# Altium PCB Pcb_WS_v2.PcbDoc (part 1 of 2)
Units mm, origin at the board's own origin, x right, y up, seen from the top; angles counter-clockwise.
Board outline 100 x 100 mm, 2 copper layers (Top Layer, Bottom Layer); 79 components, 52 nets, 324 pads, 930 vias.
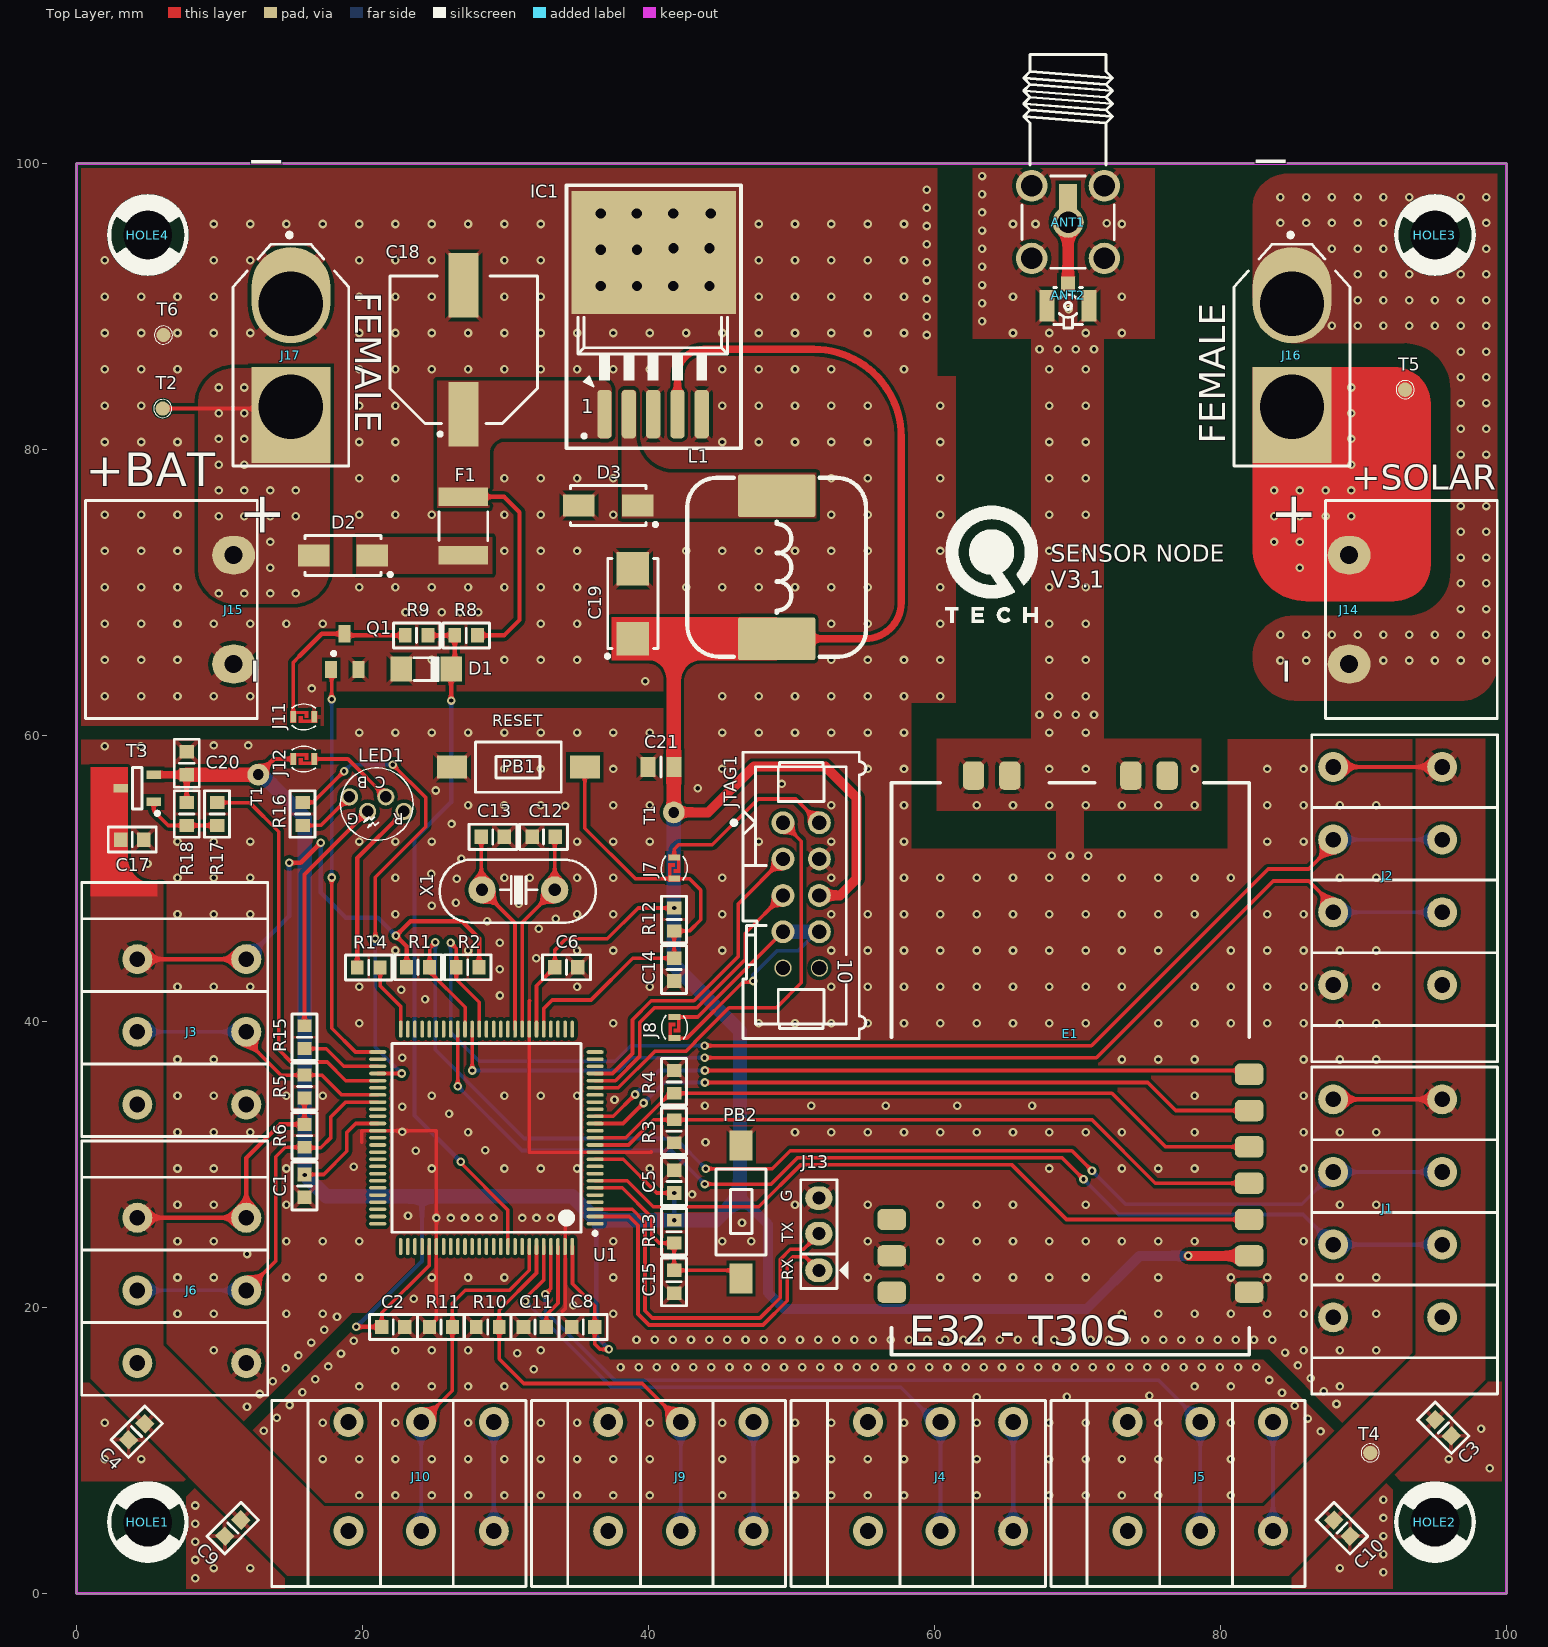
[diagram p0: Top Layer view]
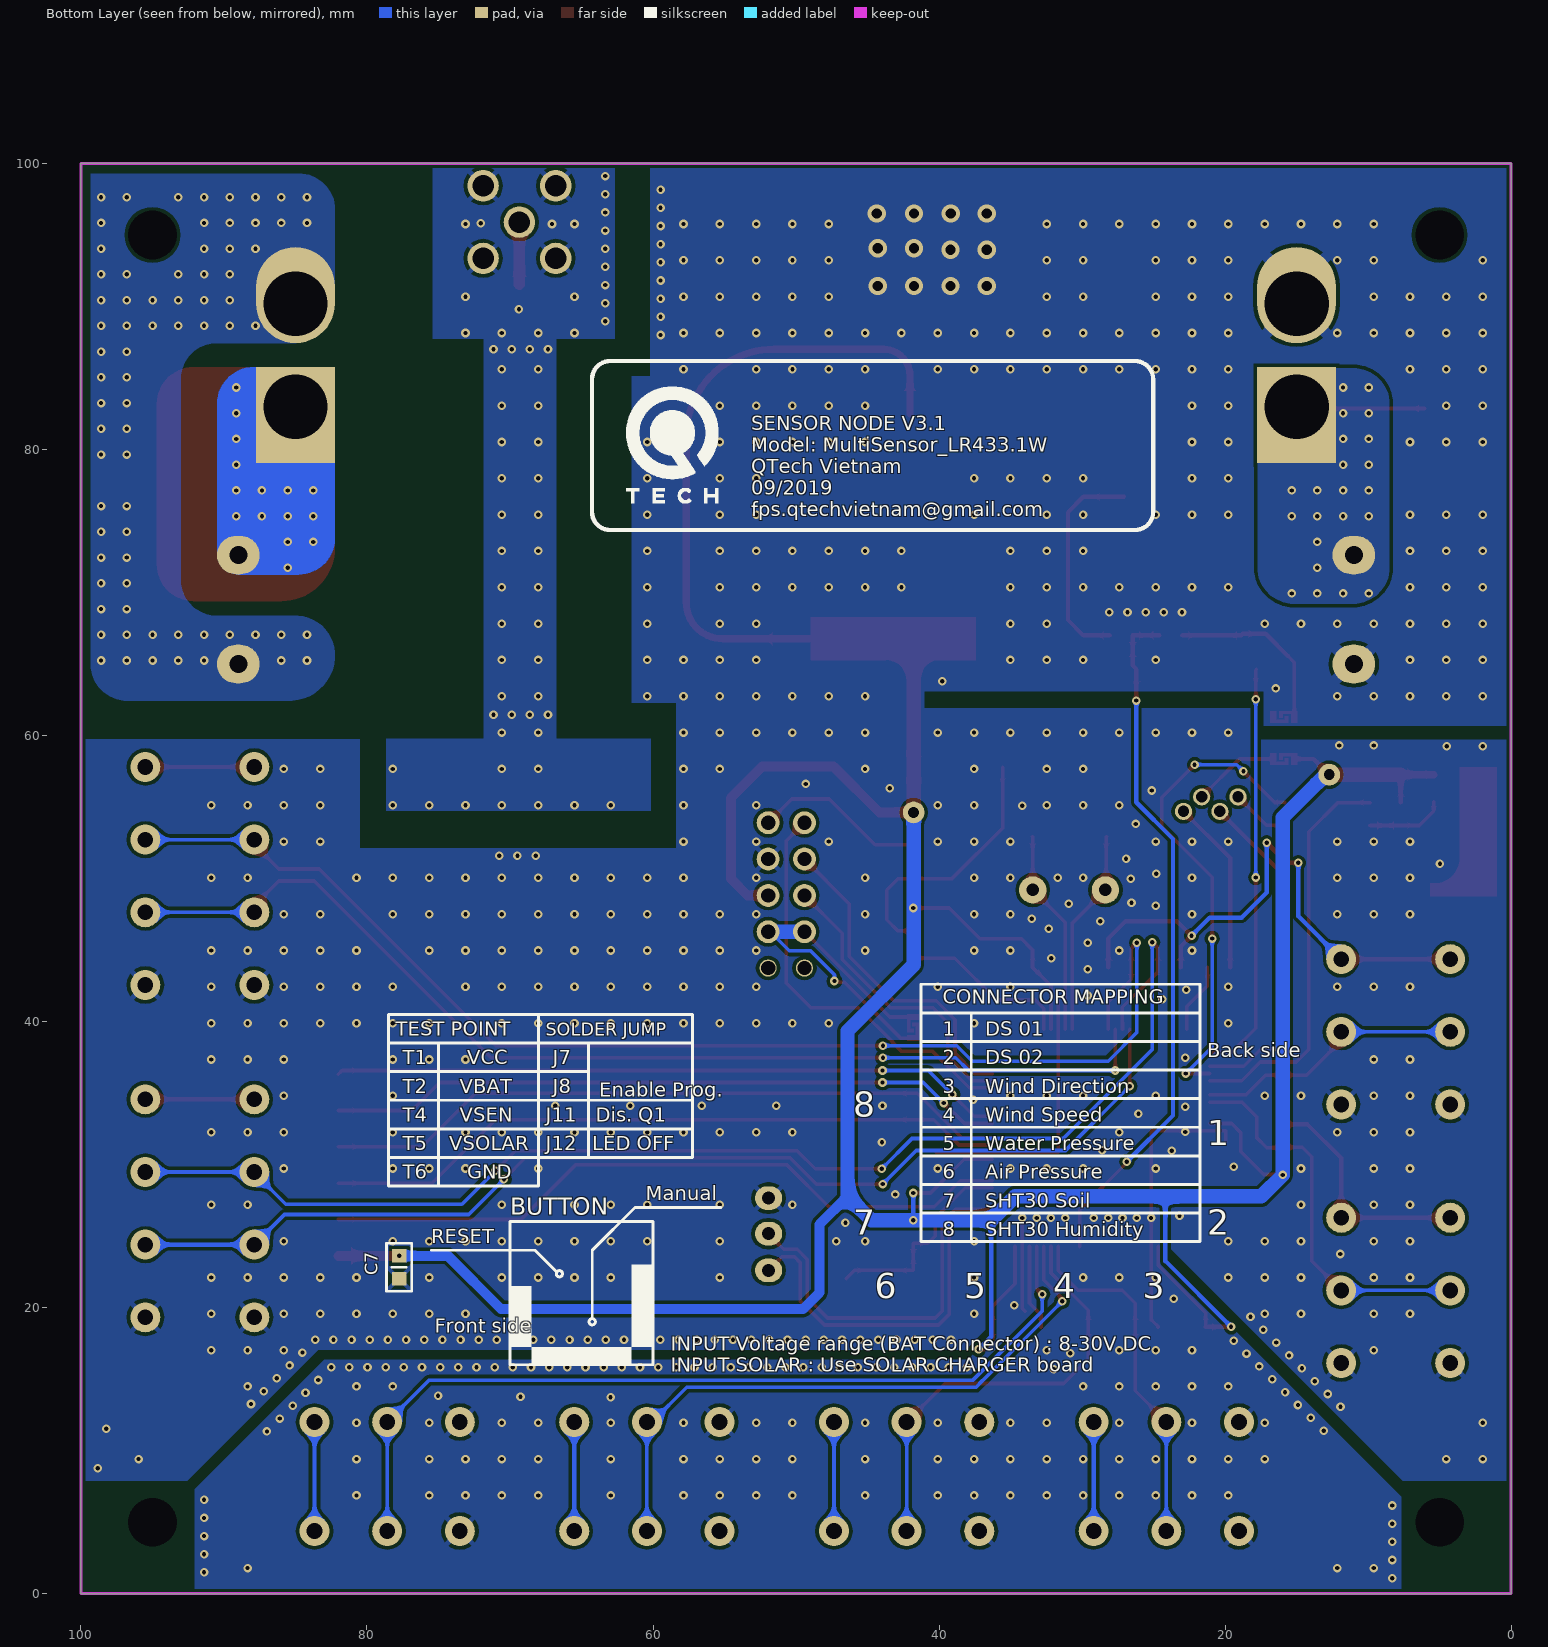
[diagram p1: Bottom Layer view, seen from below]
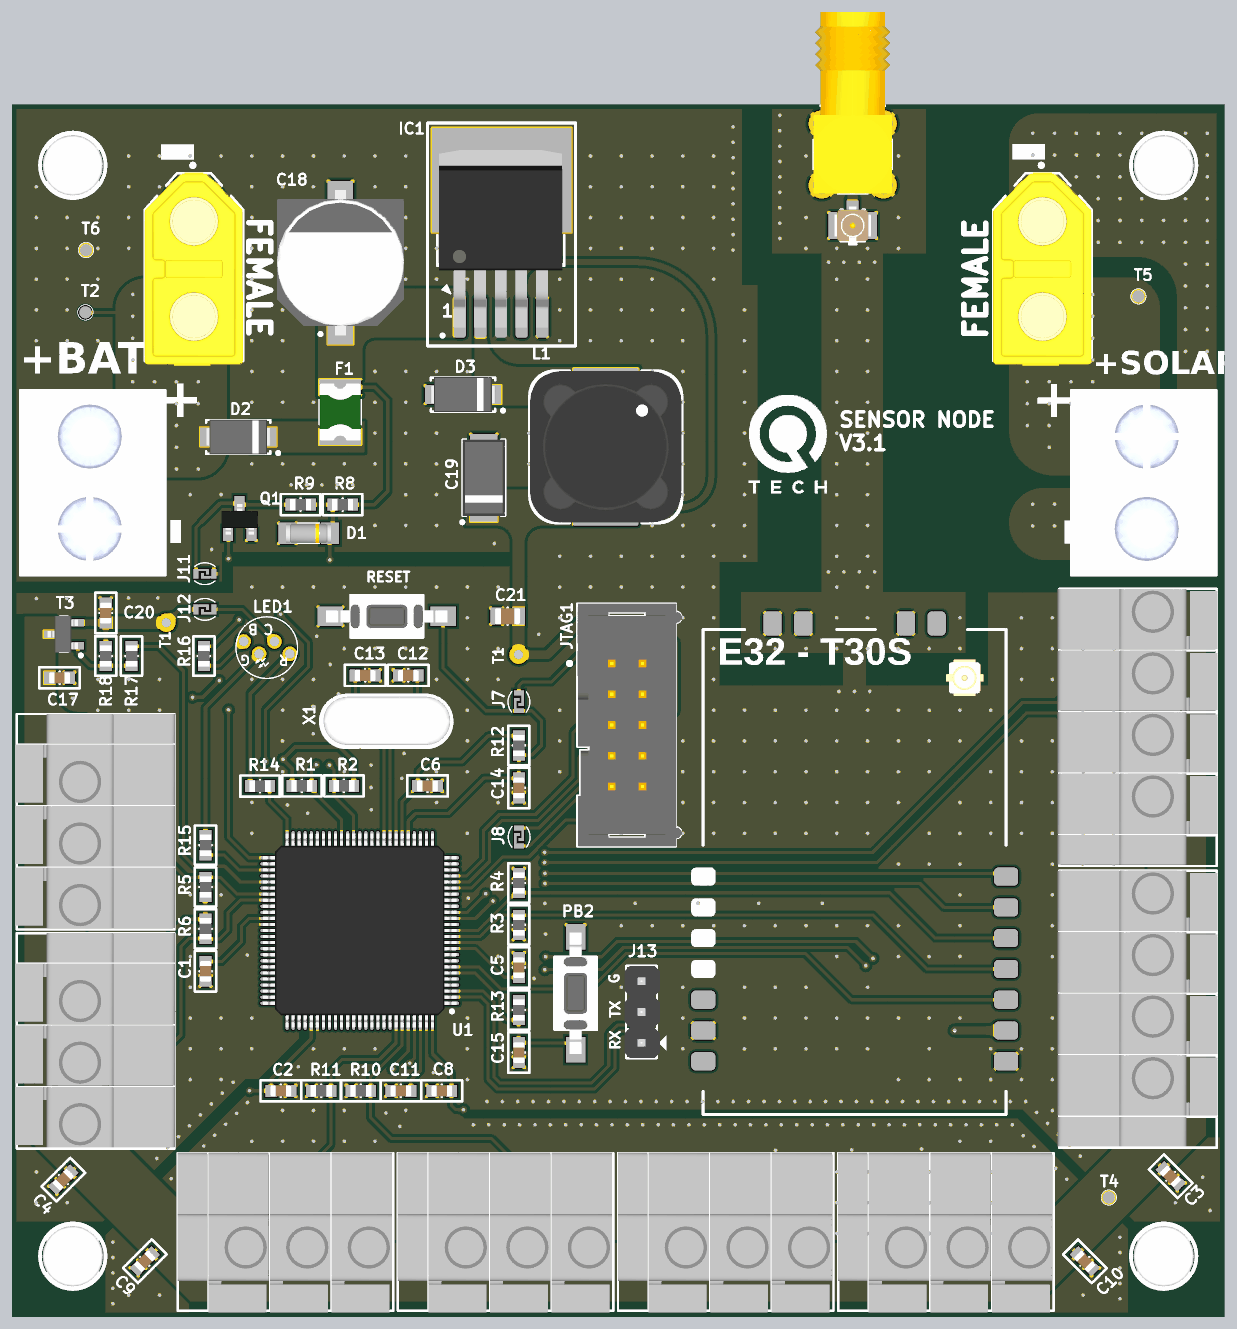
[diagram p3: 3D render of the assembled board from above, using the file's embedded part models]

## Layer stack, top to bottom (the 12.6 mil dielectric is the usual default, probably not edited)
Top Solder: solder mask 0.0102, Solder Resist, Dk 3.5
Top Layer: signal copper 0.0356
Dielectric 1: dielectric 0.32, FR-4, Dk 4.8
Bottom Layer: signal copper 0.0356
Bottom Solder: solder mask 0.0102, Solder Resist, Dk 3.5

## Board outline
0,0 0,100 100,100 100,0

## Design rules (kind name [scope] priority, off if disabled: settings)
Clearance [All] p1: gap=0.24 ignorepadtopadclearanceinfootprint=FALSE
PolygonConnect [All] p1: thpad.connectstyle=Relief thpad.reliefconductorwidth=0.35 thpad.reliefentries=4 thpad.polygonreliefangle="45 Angle" thpad.airgapwidth=0.254 smdpad.connectstyle=Relief smdpad.reliefconductorwidth=0.3 smdpad.reliefentries=4 smdpad.polygonreliefangle="45 Angle" smdpad.airgapwidth=0.254 via.connectstyle=Direct via.reliefconductorwidth=0.254 via.reliefentries=4 via.polygonreliefangle="90 Angle" via.airgapwidth=0.254
RoomDefinition Schem_WS_v2 [InComponentClass('Schem_WS_v2')] p1: confinementstyle=ConfineIn formatcopy=TRUE lockcomponents=FALSE outline -35.052,-30.861 15.748,-30.861 15.748,-5.461 -35.052,-5.461
RoutingVias [All] p1: holewidth=0.3 width=0.6 viastyle="Through Hole" minholewidth=0.3 minwidth=0.6 maxholewidth=0.3 maxwidth=0.6
SolderMaskExpansion [All] p1: expansion=0.102 istentingtop=FALSE
Width [All] p1: maxlimit=5 minlimit=0.25 preferedwidth=0.25
30 further rules are at their usual default settings.

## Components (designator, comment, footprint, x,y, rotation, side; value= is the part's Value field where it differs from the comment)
ANT1 "Coax_1Female_1Shield" "HUBER-SUHNER_85 SMA-50-0-101/111 NE" 69.341,95.902 r90 top
ANT2 "U.FL" HIROSE_U.FL-R-SMT-1(10) 69.341,90.037 r180 top
C1 "100nF" CAPC1608X87N 15.951,28.508 r270 top
C2 "100nF" CAPC1608X87N 22.162,18.644 r0 top
C3 "100nF" CAPC1608X87N 95.58,11.595 r315 top
C4 "100nF" CAPC1608X87N 4.219,11.322 r225 top
C5 "100nF" CAPC1608X87N 41.8,28.814 r90 top
C6 "100nF" CAPC1608X87N 34.262,43.8 r0 top
C7 "100nF" CAPC1608X87N 77.75,22.82 r270 bottom
C8 "100nF" CAPC1608X87N 35.442,18.644 r180 top
C9 "100nF" CAPC1608X87N 10.943,4.584 r45 top
C10 "100nF" CAPC1608X87N 88.496,4.582 r135 top
C11 "100nF" CAPC1608X87N 32.067,18.644 r180 top
C12 "22pF" CAPC1608X87N 32.675,52.919 r0 top
C13 "22pF" CAPC1608X87N 29.119,52.919 r180 top
C14 "100nF" CAPC1608X87N 41.8,43.635 r90 top
C15 "100nF" CAPC1608X87N 41.8,21.804 r90 top
C17 "100nF" CAPC1608X87N 3.91,52.724 r180 top
C18 "470uF" CAPAE1030X1020N 27.083,86.975 r90 top
C19 "220uF" CAPMP6032X280N 38.911,69.225 r90 top value=100uF
C20 "100nF" CAPC1608X87N 7.717,58.064 r270 top
C21 "10uF" CAPC2012X135N 40.875,57.804 r0 top
D1 "BZV55-B5V1" DIOMELF3515N 24.457,64.645 r180 top
D2 "SS16" DIOM5127X229N 18.647,72.589 r180 top
D3 "SS34" DIOM5127X229N 37.191,76.083 r180 top
E1 "E32-T30S" E32-433T30S 82,56.7 r180 top locked
F1 "140mA-60V" FUSRC4632X90N 27.063,74.645 r90 top
HOLE1 "HOLE" "HOLE M3" 5,5 r0 top
HOLE2 "HOLE" "HOLE M3" 95,5 r0 top
HOLE3 "HOLE" "HOLE M3" 95,95 r0 top
HOLE4 "HOLE" "HOLE M3" 5,95 r0 top
IC1 "LM2596" TO263-5 36.931,82.475 r0 top
J1 "KF142V-4P" "CON KF142V-4P-5.08" 87.88,34.564 r270 top locked
J2 "KF142V-4P" "CON KF142V-4P-5.08" 87.88,57.804 r270 top locked
J3 "KF142V-3P" "CON KF142V-3P-5.08" 11.88,34.203 r90 top locked
J4 "KF142V-3P" "CON KF142V-3P-5.08" 65.508,12 r180 top locked
J5 "KF142V-3P" "CON KF142V-3P-5.08" 83.668,12 r180 top locked
J6 "KF142V-3P" "CON KF142V-3P-5.08" 11.88,16.123 r90 top locked
J7 "SJ2" SJ2 42.213,51.674 r270 top
J8 "SJ2" SJ2 42.232,40.523 r270 top
J9 "KF142V-3P" "CON KF142V-3P-5.08" 47.348,12 r180 top locked
J10 "KF142V-3P" "CON KF142V-3P-5.08" 29.188,12 r180 top locked
J11 "SJ2" SJ2 14.956,61.715 r0 top
J12 "SJ2" SJ2 14.956,58.768 r0 top
J13 "Jumper 3" JP3 51.918,25.146 r90 top value=J3
J14 "CON KF7.62-2P" "CON KF7.62-2P" 89,68.81 r270 top locked
J15 "CON KF7.62-2P" "CON KF7.62-2P" 11,68.81 r90 top locked
J16 "XT60-FM" XT60-FM 85,86.6 r270 top locked
J17 "XT60-FM" XT60-FM 15,86.6 r270 top locked
JTAG1 "Header 10" 3M_N2510-6002RB 50.682,48.823 r270 top
L1 "33uH" L_SMD 48.969,76.769 r0 top
LED1 "LED-RGB" LED-5MMRGBCA 22.271,55.206 r180 top
PB1 "Push Button" PB_TYCO_FSMSM 30.908,57.789 r180 top
PB2 "Push Button" PB_TYCO_FSMSM 46.482,26.689 r90 top
Q1 "C1815" SOT23 18.749,65.864 r0 top
R1 "10k" RESC1608X55N 23.898,43.8 r180 top
R2 "10k" RESC1608X55N 27.366,43.8 r0 top
R3 "10k" RESC1608X55N 41.8,32.332 r90 top
R4 "10k" RESC1608X55N 41.8,35.786 r270 top
R5 "4k7" RESC1608X55N 15.951,35.458 r90 top
R6 "4k7" RESC1608X55N 15.947,32.013 r270 top
R8 "10k" RESC1608X55N 27.261,67.007 r180 top value=2M
R9 "4.7k" RESC1608X55N 23.794,67.007 r180 top value=1M
R10 "10k" RESC1608X55N 28.766,18.644 r180 top value=160
R11 "10k" RESC1608X55N 25.489,18.644 r180 top value=160
R12 "10k" RESC1608X55N 41.8,47.14 r90 top
R13 "10k" RESC1608X55N 41.8,25.309 r90 top
R14 "1k" RESC1608X55N 20.443,43.786 r180 top
R15 "1k" RESC1608X55N 15.951,38.909 r90 top
R16 "1k" RESC1608X55N 15.82,54.514 r270 top
R17 "1k" RESC1608X55N 9.844,54.514 r270 top
R18 "10k" RESC1608X55N 7.717,54.514 r270 top
T2 "Test Point" TP1x1r 6.043,82.865 r0 top
T3 "BSH203" SOT95P230X110-3N 4.26,56.314 r180 top
T4 "Test Point" TP1x1r 90.47,9.842 r0 top
T5 "Test Point" TP1x1r 92.911,84.186 r0 top
T6 "Test Point" TP1x1r 6.092,88.007 r0 top
U1 "ATmega2560-AU" TQFP100L 28.675,31.872 r180 top locked
X1 "16Mhz" XT2 30.908,49.207 r180 top value=4Mhz

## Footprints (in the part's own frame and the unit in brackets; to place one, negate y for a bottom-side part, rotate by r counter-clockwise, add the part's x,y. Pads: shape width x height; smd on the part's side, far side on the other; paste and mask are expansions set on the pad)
3M_N2510-6002RB [mm] "10 Contacts - Straight .100\" x .100\" Low Profile Four-Wall Header"
  round 1.6 hole 1: 1(-5.08,-1.27) 2(-5.08,1.27) 3(-2.54,-1.27) 4(-2.54,1.27) 5(0,-1.27) 6(0,1.27) 7(2.54,-1.27) 8(2.54,1.27)
  round 1.2 hole 1: 9(5.08,-1.27) 10(5.08,1.27)
  silkscreen extent -10.01,-4.85 10.01,4.52, body extent -10.01,-4.06 10.01,4.57, height 9.65
CAPAE1030X1020N [mm] "Capacitor, Aluminium Electrolytric, 10.3mm L X 10.3mm W X 10.2mm H, IPC Medium Density"
  rect 4.5x2.1 smd: 1(-4.5,0) 2(4.5,0)
  silkscreen extent -6.02,-5.15 5.15,5.15, body extent -6,-5.25 6,5.25, height 10.2
CAPC1608X87N [mm] "Chip Capacitor, Body 1.6x0.8mm IPC Medium Density"
  rect 0.95x1 smd: 1(-0.8,0) 2(0.8,0)
  silkscreen extent -1.68,-0.87 1.68,0.87, body extent -0.87,-0.47 0.88,0.48, height 0.87
CAPC2012X135N [mm] "Chip Capacitor, Body 2.0x1.25mm, IPC Medium Density"
  rect 1.05x1.4 smd: 1(-0.9,0) 2(0.9,0)
  silkscreen extent 0,-0.7 0,0.7, body extent -1.05,-0.67 1.05,0.68, height 1.25
CAPMP6032X280N [mm] "Capacitor, Polarized, Molded  Body 6.0x3.2mm, IPC Medium Density"
  rect 2.35x2.25 smd: 1(-2.45,0) 2(2.45,0)
  silkscreen extent -3.8,-1.75 3.15,1.9, body extent -3.15,-1.75 3.15,1.75, height 2.8
"CON KF7.62-2P" [mm]
  oval 2.7x3 hole 1.26: 1(-3.81,0) 2(3.81,0)
  silkscreen extent -7.62,-1.65 7.62,10.35, body extent -7.62,-1.65 7.62,10.35, height 12.4
"CON KF142V-3P-5.08" [mm]
  round 2.1 hole 1.1: 1(0,7.62) 1(0,0) 2(5.08,7.62) 2(5.08,0) 3(10.16,0) 3(10.16,7.62)
  silkscreen extent -2.25,-1.5 15.53,11.5, body extent -2.14,-1.57 15.54,11.63, height 14.23
"CON KF142V-4P-5.08" [mm]
  round 2.1 hole 1.1: 1(0,7.62) 1(0,0) 2(5.08,7.62) 2(5.08,0) 3(10.16,7.62) 3(10.16,0) 4(15.24,0) 4(15.24,7.62)
  silkscreen extent -2.25,-1.5 20.61,11.5, body extent -2.26,-1.62 20.5,11.58, height 14.22
DIOM5127X229N [mm] "DO-214-AC/SMA Molded Diode, 2-Leads, Body 5.1x2.7mm, IPC Medium Density"
  rect 2.2x1.55 smd: 1(-2.05,0) 2(2.05,0)
  silkscreen extent -3.43,-1.4 2.65,1.45, body extent -2.67,-1.45 2.68,1.45, height 2.29
DIOMELF3515N [mm] "SOD80C, MELF Diode, 2-Leads, Body 3.5x1.5mm, IPC Medium Density"
  rect 1.5x1.75 smd: 1(-1.75,0) 2(1.75,0)
  silkscreen extent -0.85,-0.8 0.85,0.8, body extent -1.85,-0.8 1.85,0.8, height 1.6
E32-433T30S [mm] "Lora-EBYTE-410~441MHz-21~30dBm-UART-SX1278-25x40mm"
  rrect50% 2x1.5 smd: 1(0,20.38) 2(0,22.92) 3(0,25.46) 4(0,28) 5(0,30.54) 6(0,33.08) 7(0,35.62) 8(24.98,35.62) 9(24.98,33.08) 10(24.98,30.54)
  rrect50% 2x1.5 on Top Overlay: 11(24.98,28) 12(24.98,25.46) 13(24.98,22.92) 14(24.98,20.38)
  rrect50% 1.5x2 smd: 15(19.27,-0.5) 16(16.73,-0.5) 17(8.27,-0.5) 18(5.73,-0.5)
  silkscreen extent 0,0 25,40, body extent 0,0 25,40, height 3.5
FUSRC4632X90N [mm] "Chip Resettable Fuse, 2-Leads, Body 4.6x3.2mm, IPC Medium Density"
  rect 1.3x3.45 smd: 1(-2.05,0) 2(2.05,0)
  silkscreen extent -1,-1.7 1,1.7, body extent -2.36,-1.7 2.37,1.71, height 0.89
HIROSE_U.FL-R-SMT-1(10) [mm] "Up to 6GHz Ultra Small Surface Mount Male Coaxial Connectors U.FL Series"
  rect 1x1.05 smd: 1(0,-1.525)
  rect 1.05x2.2 smd: 2(-1.475,0) 2(1.475,0)
  silkscreen extent -1,-1.3 1,1.55, body extent -1.5,-1.55 1.5,1.55, height 1.25
"HOLE M3" [mm]
  round 3.2 hole 3.4 mask+0.1: 1(0,0)
  Top Layer pour cut-out: -2.846,0.006 -2.628,1.101 -2.007,2.029 -1.077,2.646 0.019,2.859 0.019,2.859 1.117,2.635 2.042,2.003 2.649,1.062 2.845,-0.041 2.845,-0.041 2.628,-1.12 2.013,-2.033 1.094,-2.64 0.012,-2.845 0.012,-2.845 -1.086,-2.638 -2.017,-2.021 -2.636,-1.091 -2.846,0.006
  silkscreen extent -2.7,-2.7 2.7,2.7, body extent -2.5,-2.5 2.5,2.5, height 1.73
"HUBER-SUHNER_85 SMA-50-0-101/111 NE" [mm] "50 Ohm SMA Right Angle PCB Jack"
  round 2.2 hole 1.5: 1(0,0) 2(-2.54,-2.54) 2(-2.54,2.54) 2(2.54,-2.54) 2(2.54,2.54)
  silkscreen extent -3.23,-3.23 11.73,3.23, body extent -3.23,-3.23 11.73,3.23, height 9.6
JP3 [mil] "Jumper 3"
  oval 65x75 hole 36: 1(-100,0) 2(1,0) 3(99,0)
  silkscreen extent -150,-81 150,50, body extent -150,-60 150,55, height 355
L_SMD [mm]
  rrect10% 5.4x3 smd mask+0.1: 1(0,0) 2(0,-10)
  silkscreen extent -6.25,-11.25 6.25,1.25, body extent -6.25,-11.25 6.25,1.25, height 6.7
LED-5MMRGBCA [mm]
  round 1.2 hole 0.8: A(0.635,-0.508) B(1.905,0.508) G(-0.635,0.508) R(3.175,-0.508)
  silkscreen extent -1.27,-2.54 3.81,2.54, body extent -1.4,-2.67 3.91,2.66, height 9.4
PB_TYCO_FSMSM [mm] "Body 3.5x6.0mm, Pushbutton Switch,  TYCO FSMSM Serie"
  rect 2.1x1.6 smd: 1(-4.65,0) 2(4.65,0)
  silkscreen extent -3,-1.75 3,1.75, body extent -5,-1.75 5,1.75, height 4.3
RESC1608X55N [mm] "Chip Resistor, EIA 0603, Metric 1608, Body 1.6x0.8mm, IPC Medium Density"
  rect 0.9x1 smd: 1(-0.8,0) 2(0.8,0)
  silkscreen extent -1.63,-0.87 1.63,0.87, body extent -0.87,-0.47 0.88,0.48, height 0.55
SJ2 [mil] "Solder Jump"
  rect 16x32 smd mask+4: 1(8,-16) 2(66,-16)
  Top Layer region: 0,0 50,0 50,-18 40,-18 40,-8 16,-8 16,-32 0,-32
  Top Layer region: 74,-32 24,-32 24,-14 34,-14 34,-24 58,-24 58,0 74,0
  silkscreen extent 4,-52 70,20
SOT23 [mm] "SOT 23 _ 1-3-2"
  rect 0.85x1.2 smd: 1(-0.94,-1.245) 2(0.985,-1.25) 3(0.005,1.25)
  silkscreen extent -0.88,-0.25 -0.64,0, body extent -1.47,-1.33 1.53,1.17, height 1.06
SOT95P230X110-3N [mm] "SOT23, 3 pin, Pitch 0.95mm - 1.3mm W X 2.9mm L X 1.1mm H, IPC Medium Density"
  rect 1x0.6 smd: 1(-1.15,0.95) 2(-1.15,-0.95) 3(1.15,0)
  silkscreen extent -1.53,-1.45 0.33,1.87, body extent -1.17,-1.5 1.33,1.5, height 1.1
TO263-5 [mm]
  rrect50% 1x3.4 smd: 1(0,0) 2(1.7,0) 4(5.1,0) 5(6.8,0)
  rrect50% 1x3.4 smd mask+0: 3(3.4,0)
  rect 11.5x8.634 smd: 6(3.45,11.302)
  silkscreen extent -2.66,-2.38 9.54,16.02, body extent -1.71,-0.87 8.45,13.77, height 4.57
TP1x1r [mm]
  round 1 smd: 1(0,0)
  silkscreen extent -0.63,-0.63 0.64,0.63
TQFP100L [mm] "TQFP, 100-Leads, Body 14.00x14.00mm, Pitch 0.50mm, IPC High Density"
  oval 1.2x0.25 smd: 1(-7.6,6) 2(-7.6,5.5) 3(-7.6,5) 4(-7.6,4.5) 5(-7.6,4) 6(-7.6,3.5) 7(-7.6,3) 8(-7.6,2.5) 9(-7.6,2) 10(-7.6,1.5) 11(-7.6,1) 12(-7.6,0.5) 13(-7.6,0) 14(-7.6,-0.5) 15(-7.6,-1) 16(-7.6,-1.5) 17(-7.6,-2) 18(-7.6,-2.5) 19(-7.6,-3) 20(-7.6,-3.5) 21(-7.6,-4) 22(-7.6,-4.5) 23(-7.6,-5) 24(-7.6,-5.5) 25(-7.6,-6) 51(7.6,-6) 52(7.6,-5.5) 53(7.6,-5) 54(7.6,-4.5) 55(7.6,-4) 56(7.6,-3.5) 57(7.6,-3) 58(7.6,-2.5) 59(7.6,-2) 60(7.6,-1.5) 61(7.6,-1) 62(7.6,-0.5) 63(7.6,0) 64(7.6,0.5) 65(7.6,1) 66(7.6,1.5) 67(7.6,2) 68(7.6,2.5) 69(7.6,3) 70(7.6,3.5) 71(7.6,4) 72(7.6,4.5) 73(7.6,5) 74(7.6,5.5) 75(7.6,6)
  oval 0.25x1.2 smd: 26(-6,-7.6) 27(-5.5,-7.6) 28(-5,-7.6) 29(-4.5,-7.6) 30(-4,-7.6) 31(-3.5,-7.6) 32(-3,-7.6) 33(-2.5,-7.6) 34(-2,-7.6) 35(-1.5,-7.6) 36(-1,-7.6) 37(-0.5,-7.6) 38(0,-7.6) 39(0.5,-7.6) 40(1,-7.6) 41(1.5,-7.6) 42(2,-7.6) 43(2.5,-7.6) 44(3,-7.6) 45(3.5,-7.6) 46(4,-7.6) 47(4.5,-7.6) 48(5,-7.6) 49(5.5,-7.6) 50(6,-7.6) 76(6,7.6) 77(5.5,7.6) 78(5,7.6) 79(4.5,7.6) 80(4,7.6) 81(3.5,7.6) 82(3,7.6) 83(2.5,7.6) 84(2,7.6) 85(1.5,7.6) 86(1,7.6) 87(0.5,7.6) 88(0,7.6) 89(-0.5,7.6) 90(-1,7.6) 91(-1.5,7.6) 92(-2,7.6) 93(-2.5,7.6) 94(-3,7.6) 95(-3.5,7.6) 96(-4,7.6) 97(-4.5,7.6) 98(-5,7.6) 99(-5.5,7.6) 100(-6,7.6)
  silkscreen extent -7.73,-6.6 6.6,6.8, body extent -8,-8 8,8, height 1.2
XT2 [mil] "Footpin for Crystal 2 pin"
  round 75 hole 34: 1(-100,0) 2(100,0)
  silkscreen extent -213,-83 217,90, body extent -216,-87 216,90, height 144
XT60-FM [mm]
  oval 6.716x5.516 hole 4.5 copper offset -0.6,0: 1(-3.6,0)
  rect 6.716x5.516 hole 4.5 copper offset 0.6,0: 2(3.6,0)
  silkscreen extent -8.55,-4.05 7.75,4.05, body extent -7.81,-4.07 8.12,4.06, height 15.5

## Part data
ANT1: library part HUBER-SUHNER_85_SMA-50-0-101/111_NE, Manufacturer=HUBER+SUHNER, Manufacturer Part Number=85_SMA-50-0-101/111_NE
ANT2: library part HIROSE_U.FL-R-SMT-1(10), Manufacturer="HIROSE (HRS)", Manufacturer Part Number=U.FL-R-SMT-1(10)
C1 C2 C3 C4 C5 C6 C7 C8 C9 C10 C11 C14 C15 C17 C20: library part CC0603_100NF_50V_10%_X7R, "Non-polarised capacitor", Case=0603, Manufacturer=GENERIC, Manufacturer1 ComponentHeight=0.87mm, Manufacturer1 Example=PHYCOMP, Manufacturer1 Part Number=223858615649, Tolerance=±10%, Voltage=50V
C12 C13: library part CC0603_22PF_50V_5%_NP0, "Non-polarised capacitor", Case=0603, Manufacturer=GENERIC, Manufacturer1 ComponentHeight=0.87mm, Manufacturer1 Example=PHYCOMP, Manufacturer1 Part Number=223886715229, Tolerance=±5%, Voltage=50V
C18: library part CAE1030-1020_470UF_25V_20%, "Polarised capacitor", Case=G, Manufacturer=GENERIC, Manufacturer1 ComponentHeight=10.2mm, Manufacturer1 Example=PANASONIC, Manufacturer1 Part Number=EEEFK1E471AP, Tolerance=±20%, Voltage=25V
C19: library part CTE6032-28_100UF_6.3V_10%_LESR0075, "Polarised capacitor", Case=C, Manufacturer=GENERIC, Manufacturer1 ComponentHeight=2.8mm, Manufacturer1 Example=AVX, Manufacturer1 Part Number=TPSC107K006R0075, Tolerance=±10%, Voltage=6.3V
C21: library part CC0805_10UF_16V_10%_X5R, "Non-polarised capacitor", Case=0805, Manufacturer=GENERIC, Manufacturer1 ComponentHeight=1.4mm, Manufacturer1 Example=KEMET, Manufacturer1 Part Number=C0805C106K4PAC, Tolerance=±10%, Voltage=16V
D1: "Zener Diode", Case=SOD-80C, Manufacturer="NXP SEMICONDUCTORS", Power=500mW, Voltage=5V1
D2: "Schottky Diode", Case=DO-214AC, Manufacturer="VISHAY GENERAL SEMICONDUCTOR", Power=1A, Voltage=60V
D3: library part SS16, "Schottky Diode", Case=DO-214AC, Manufacturer="VISHAY GENERAL SEMICONDUCTOR", Power=1A, Voltage=60V
E1: library part E32-433T30S, "Lora Ebyte E32-T30S Module"
F1: library part FUSR1812_TYCO-MINISMDC014F, "Fuse", Manufacturer="TYCO ELECTRONICS", Manufacturer Part Number=miniSMDC014F
HOLE1 HOLE2 HOLE3 HOLE4: library part "HOLE M3"
IC1: library part LM2596-5V
J1 J2: library part "CON KF142V-4P-5.08", "CON KF142V-4P-5.08"
J3 J4 J5 J6 J9 J10: library part "CON KF142V-3P-5.08", "CON KF142V-3P-5.08"
J7 J8 J11 J12: "Solder Jump2"
J13: library part JP3
J16 J17: Package="Package Analog Devices"
JTAG1: library part 3M_N2510-6002RB, "Connector 10 Male", Manufacturer=3M, Manufacturer Part Number=N2510-6002RB
L1: library part "L_SMD 33uH"
PB1 PB2: "Push-Button Switch SPDT", Manufacturer="TYCO ELECTRONICS", Manufacturer Part Number="FSMSM or 1437566-3", Part Number=PB_TYCO_FSMSM
Q1: "Q2SC1815", PSpiceTemplate="Q^@REFDES %c %b %e @MODEL"
R1 R2 R3 R4 R12 R13 R18: library part R0603_10K_1%_0.1W_100PPM, "Resistor - 1%", Case=0603, Manufacturer=GENERIC, Manufacturer1 ComponentHeight=0.55mm, Manufacturer1 Example="NIC COMPONENT", Manufacturer1 Part Number=NRC06F1002TRF, Power=0.1W, Tolerance=±1%
R5 R6: library part R0603_4K7_1%_0.1W_100PPM, "Resistor - 1%", Case=0603, Manufacturer=GENERIC, Manufacturer1 ComponentHeight=0.55mm, Manufacturer1 Example="NIC COMPONENT", Manufacturer1 Part Number=NRC06F4701TRF, Power=0.1W, Tolerance=±1%
R8: library part R0603_2M_1%_0.1W_100PPM, "Resistor - 1%", Case=0603, Manufacturer=GENERIC, Manufacturer1 ComponentHeight=0.55mm, Manufacturer1 Example="NIC COMPONENT", Manufacturer1 Part Number=NRC06F2004TRF, Power=0.1W, Tolerance=±1%
R9: library part R0603_1M_1%_0.1W_100PPM, "Resistor - 1%", Case=0603, Manufacturer=GENERIC, Manufacturer1 ComponentHeight=0.55mm, Manufacturer1 Example="NIC COMPONENT", Manufacturer1 Part Number=NRC06F1004TRF, Power=0.1W, Tolerance=±1%
R10 R11: library part R0603_160R_1%_0.1W_100PPM, "Resistor - 1%", Case=0603, Manufacturer=GENERIC, Manufacturer1 ComponentHeight=0.55mm, Manufacturer1 Example="NIC COMPONENT", Manufacturer1 Part Number=NRC06F1600TRF, Power=0.1W, Tolerance=±1%
R14 R15 R16 R17: library part R0603_1K_1%_0.1W_100PPM, "Resistor - 1%", Case=0603, Manufacturer=GENERIC, Manufacturer1 ComponentHeight=0.55mm, Manufacturer1 Example="NIC COMPONENT", Manufacturer1 Part Number=NRC06F1001TRF, Power=0.1W, Tolerance=±1%
T2 T4 T5 T6: library part "TP R1x1", "Test Point Round 1x1 mm"
T3: "P-CHANNEL MOSFET WITH DIODE", Case=SOT23-3, Manufacturer="NXP SEMICONDUCTORS"
U1: "8-bit AVR Microcontroller, 4.5-5.5V, 256KB Flash, 4KB EEPROM, 8KB SRAM, 86 GPIO pins, 100-pin TQFP, Industrial Grade (-40°C to 85°C), Pb-Free", Supplier Part Number 1=ATMEGA2560-16AUR-ND
X1: library part XT2, "Crystal, 32.768 KHz, -40 to 85 degC, 3.2 x 1.5 x 0.9 mm SMD"

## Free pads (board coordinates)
  rect 1.27x2.1 smd: 4(69.341,97.502)
  round 1.524 hole 0.762: TP-VCC(12.717,57.264) TP-VCC(41.775,54.628)

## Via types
v1: diameter 0.6, hole 0.3, Top Layer to Bottom Layer, tented both sides, 918 vias
v2: diameter 1.27, hole 0.711, Top Layer to Bottom Layer, 12 vias

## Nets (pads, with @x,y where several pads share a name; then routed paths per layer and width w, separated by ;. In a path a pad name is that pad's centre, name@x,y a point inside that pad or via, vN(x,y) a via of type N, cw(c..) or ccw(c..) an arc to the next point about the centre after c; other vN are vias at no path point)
A0-Air: J5.2 U1.97 | length 61.3
  Top Layer w0.254: v1(32.791,20.93) 33.175,21.313 U1.97@33.175,24.272
  Bottom Layer w0.254: v1(32.791,20.93) 32.791,19.766 37.624,14.933 75.655,14.933 J5.2@78.588,12 J5.2@78.588,4.38
A1-Water: J4.2 U1.96 | length 44.5
  Top Layer w0.254: v1(31.394,20.447) 31.394,20.65 32.675,21.931 U1.96@32.675,24.272
  Bottom Layer w0.254: v1(31.394,20.447) 36.945,14.897 36.962,14.897 37.42,14.439 57.638,14.439 60.077,12 J4.2@60.428,12 J4.2@60.428,4.38
A2Speed: J9.2 R10.1 U1.95 | length 31.1
  Top Layer w0.254: U1.95@32.175,24.272 32.175,22.416 29.566,19.806 R10.1@29.566,18.644 29.566,16.413 31.286,14.693 39.575,14.693 J9.2@42.268,12
  Bottom Layer w0.254: J9.2@42.268,4.38 J9.2@42.268,12
A3Direct: J10.2 R11.1 U1.94 | length 24.8
  Top Layer w0.254: J10.2@24.108,12 26.289,14.181 R11.1@26.289,18.644 26.289,20.314 27.196,21.221 30.282,21.221 31.675,22.614 U1.94@31.675,24.272
  Bottom Layer w0.254: J10.2@24.108,4.38 J10.2@24.108,12
A6Pin: D1.1 R8.2 R9.1 U1.91 | length 48.5
  Top Layer w0.25: v1(26.873,30.201) 26.873,30.132 30.175,26.83 U1.91@30.175,24.272
  Top Layer w0.3: R9.1@24.594,67.007 R8.2@26.461,67.007 26.461,64.899 D1.1@26.207,64.645 v1(26.207,62.444)
  Bottom Layer w0.3: v1(26.207,62.444) 26.207,55.332 23.643,52.768 23.643,33.439 26.881,30.201 v1(26.873,30.201)
CheckLevel: C18.1 F1.2 IC1.1 R8.1 | length 15.3
  Top Layer w0.3: F1.2@27.063,76.695 29.912,76.695 30.986,75.62 30.986,68.08 29.913,67.007 R8.1@28.061,67.007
